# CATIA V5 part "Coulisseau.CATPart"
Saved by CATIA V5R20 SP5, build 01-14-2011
Part number: Coulisseau
Bounding box of the stored display mesh (mm): x -20 to 20, y -25 to 25, z 0 to 20
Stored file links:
  F:\IAO_bmadec\bmadecf\Coulisseau.CATPart
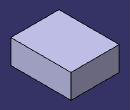
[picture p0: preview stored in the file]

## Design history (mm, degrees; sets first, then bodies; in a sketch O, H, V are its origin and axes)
Body1 (main body)
  Sketch1 on zx-plane, origin (0, 0, 0), H (-1, 0, 0), V (0, 0, 1)
    line L1 (-20, 20) -> (20, 20)
    line L2 (20, 20) -> (20, 0)
    line L3 (20, 0) -> (-20, 0)
    line L4 (-20, 0) -> (-20, 20)
    distance V L2 = 20
    distance L1 L3 = 20
    horizontal: L1 H, L3 H
    vertical: L2 V, L4 V
    symmetry: L4 L2 V
    coincidence: L3 H
  Pad1: profile Sketch1, direction (0, 1, 0), length 25, opposite side length 25
  Sketch2 on face of Pad1 from Sketch1.L3, origin (-7.3971, 9.2464, 0), H (1, 0, 0), V (0, -1, 0)
    point P1 (7.3971, 9.2464)
    reference intersected line E1 through (0, 9.2464) direction (1, 0) from zx-plane
    reference intersected line E2 through (7.3971, 0) direction (0, 1) from yz-plane
    coincidence: P1 E1, P1 E2
  Hole1: placed by Sketch2, at (0, 0, 0) direction (0, 0, 1), diameter 20, depth 10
